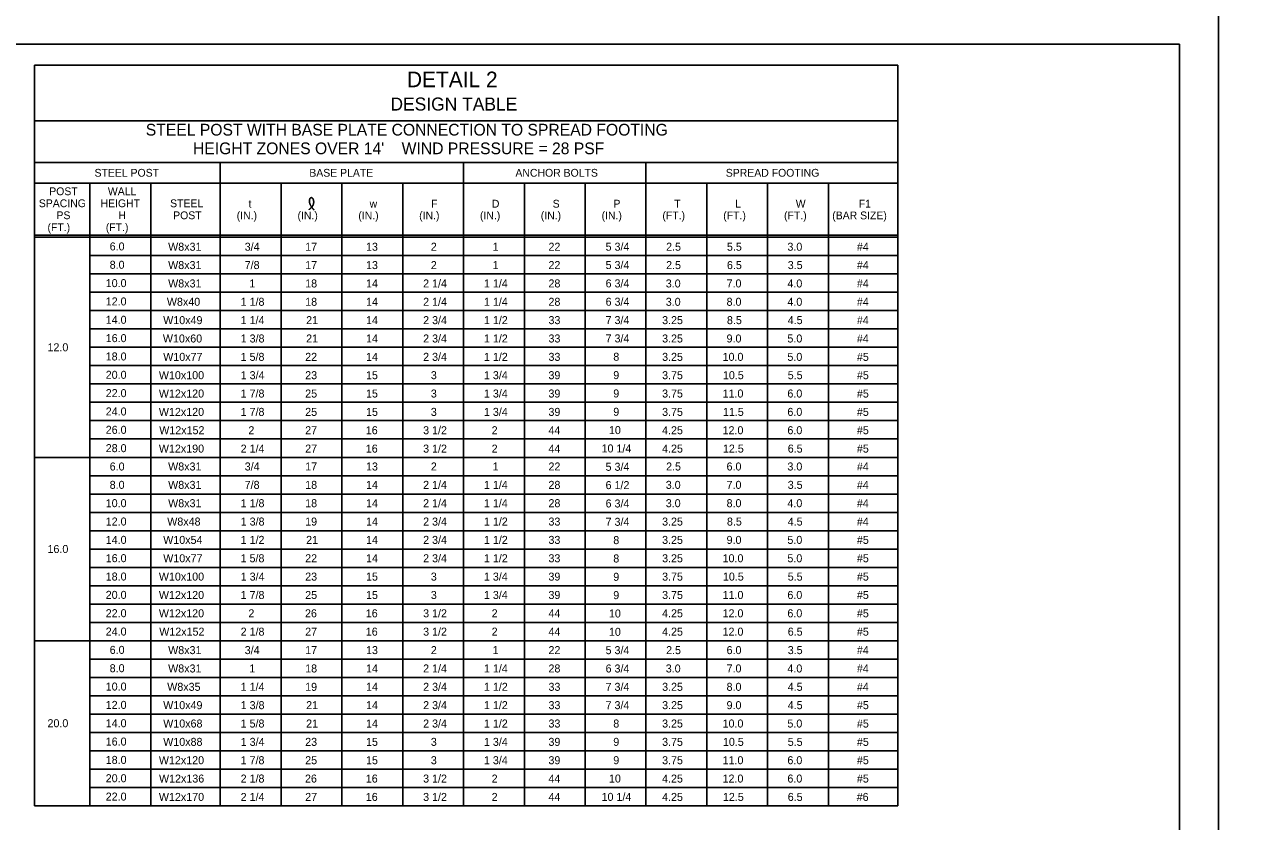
# Model space of a CAD drawing. Extents: x 3475 to 6558, y -3780 to 1166.
# Drawn here: x 4985.3 to 5460.5, y -929.6 to -623.8 of the extents above; entities that cross this region are included whole.
import ezdxf

# ---------------------------------------------------------------- set-up
doc = ezdxf.new("R2010")
doc.units = 0
for name, color, linetype in [('1', 7, 'Continuous'), ('2', 7, 'Continuous'), ('PLT-BNDY', 7, 'Continuous')]:
    doc.layers.add(name, color=color, linetype=linetype)

msp = doc.modelspace()

# ---------------------------------------------------------------- linework, layer by layer
at = {"layer": '1'}
for p, q in [((5320.34, -639.3), (4989.01, -639.3)), ((4989.01, -639.3), (4989.01, -923.63)), ((5320.34, -639.3), (5320.34, -923.63)), ((5320.34, -660.64), (4989.01, -660.64)), ((4989.01, -676.64), (5320.34, -676.64)), ((5060.34, -676.64), (5060.34, -923.63)), ((5153.67, -676.64), (5153.67, -923.63)), ((5223.68, -676.64), (5223.68, -923.63)), ((4989.01, -684.64), (5320.34, -684.64)), ((4989.01, -684.64), (5057.01, -684.64)), ((4989.01, -684.64), (5057.01, -684.64)), ((5010.34, -923.63), (5010.34, -684.64)), ((5033.67, -684.64), (5033.67, -923.63)), ((5083.67, -684.64), (5083.67, -923.63)), ((5107.01, -684.64), (5107.01, -923.63)), ((5130.34, -684.64), (5130.34, -923.63)), ((5177.01, -684.64), (5177.01, -923.63)), ((5200.34, -684.64), (5200.34, -923.63)), ((5247.01, -684.64), (5247.01, -923.63)), ((5270.34, -684.64), (5270.34, -923.63)), ((5293.68, -684.64), (5293.68, -923.63)), ((4989.01, -704.64), (5320.34, -704.64)), ((4989.01, -705.39), (5320.34, -705.39)), ((5010.34, -712.43), (5320.34, -712.43)), ((5010.34, -719.47), (5320.34, -719.47)), ((5010.34, -726.51), (5320.34, -726.51)), ((5010.34, -733.55), (5320.34, -733.55)), ((5010.34, -740.59), (5320.34, -740.59)), ((5010.34, -747.63), (5320.34, -747.63)), ((5010.34, -754.67), (5320.34, -754.67)), ((5010.34, -761.71), (5320.34, -761.71)), ((5010.34, -768.75), (5320.34, -768.75)), ((5010.34, -775.79), (5320.34, -775.79)), ((5010.34, -782.83), (5320.34, -782.83)), ((4989.01, -789.87), (5320.34, -789.87)), ((5010.34, -796.91), (5320.34, -796.91)), ((5010.34, -803.95), (5320.34, -803.95)), ((5010.34, -810.99), (5320.34, -810.99)), ((5010.34, -818.03), (5320.34, -818.03)), ((5010.34, -825.07), (5320.34, -825.07)), ((5010.34, -832.11), (5320.34, -832.11)), ((5010.34, -839.15), (5320.34, -839.15)), ((5010.34, -846.19), (5320.34, -846.19)), ((5010.34, -853.23), (5320.34, -853.23)), ((4989.01, -860.27), (5320.34, -860.27)), ((5010.34, -867.31), (5320.34, -867.31)), ((5010.34, -874.35), (5320.34, -874.35)), ((5010.34, -881.39), (5320.34, -881.39)), ((5010.34, -888.43), (5320.34, -888.43)), ((5010.34, -895.47), (5320.34, -895.47)), ((5010.34, -902.51), (5320.34, -902.51)), ((5010.34, -909.55), (5320.34, -909.55)), ((5010.34, -916.59), (5320.34, -916.59)), ((4989.01, -923.63), (5320.34, -923.63))]:
    msp.add_line(p, q, dxfattribs=at)
msp.add_spline([(5094.4, -694.81), (5094.6, -694.64), (5094.73, -694.51), (5094.93, -694.31), (5095.09, -694.14), (5095.37, -693.94), (5095.56, -693.68), (5095.74, -693.49), (5095.86, -693.26), (5095.97, -693), (5096.05, -692.77), (5096.13, -692.54), (5096.15, -692.35), (5096.19, -692.1), (5096.2, -691.88), (5096.19, -691.63), (5096.14, -691.38), (5096.09, -691.14), (5096.03, -690.91), (5095.95, -690.68), (5095.87, -690.54), (5095.78, -690.44), (5095.68, -690.35), (5095.59, -690.26), (5095.47, -690.2), (5095.39, -690.18), (5095.22, -690.18), (5095.13, -690.2), (5094.98, -690.26), (5094.88, -690.34), (5094.82, -690.42), (5094.76, -690.54), (5094.69, -690.66), (5094.65, -690.8), (5094.61, -690.91), (5094.58, -691.15), (5094.55, -691.32), (5094.58, -691.51), (5094.58, -691.71), (5094.61, -691.98), (5094.64, -692.22), (5094.67, -692.38), (5094.75, -692.6), (5094.85, -692.83), (5094.94, -693.03), (5095.04, -693.22), (5095.16, -693.45), (5095.35, -693.63), (5095.47, -693.84), (5095.61, -694), (5095.72, -694.18), (5095.86, -694.35), (5095.99, -694.52), (5096.1, -694.63), (5096.21, -694.76), (5096.32, -694.93)], degree=3, dxfattribs=at)
at = {"layer": '2'}
for p, q in [((4642.34, -631.31), (5428.34, -631.31)), ((5428.34, -631.31), (5428.34, -1195.31))]:
    msp.add_line(p, q, dxfattribs=at)
at = {"layer": 'PLT-BNDY'}
for points in [[(4602.34, -616.31), (5443.34, -616.31), (5443.34, -1210.31), (4602.34, -1210.31)], [(5443.34, -616.31), (6284.34, -616.31), (6284.34, -1210.31), (5443.34, -1210.31)]]:
    msp.add_lwpolyline(points, close=True, dxfattribs=at)

# ---------------------------------------------------------------- texts
at = {"layer": '1'}
for s, height, p in [('DETAIL 2', 6, (5131.97, -647.79)), ('DESIGN TABLE', 5.0001, (5125.64, -656.74)), ('STEEL POST WITH BASE PLATE CONNECTION TO SPREAD FOOTING', 4.5001, (5031.77, -666.34)), ("HEIGHT ZONES OVER 14'    WIND PRESSURE = 28 PSF", 4.5001, (5049.88, -673.5)), ('STEEL POST', 3, (5012.11, -682.14)), ('BASE PLATE', 3, (5094.51, -682.14)), ('ANCHOR BOLTS', 3, (5173.58, -682.14)), ('SPREAD FOOTING', 3, (5254.3, -682.14)), ('POST', 3, (4994.73, -689.24)), ('WALL', 3, (5017.22, -689.24)), ('SPACING', 3, (4990.73, -693.84)), ('HEIGHT', 3, (5014.4, -693.84)), ('STEEL', 3, (5041.11, -693.86)), ('t', 3, (5071.17, -694)), ('w', 3, (5117.65, -694)), ('F', 3, (5141.26, -694)), ('D', 3, (5164.54, -694)), ('S', 3, (5187.88, -694)), ('P', 3, (5211.2, -694)), ('T', 3, (5234.49, -694)), ('L', 3, (5257.94, -694)), ('W', 3, (5281.14, -694)), ('F1', 3, (5305.31, -694)), ('PS', 3, (4997.49, -698.44)), ('H', 3, (5021.27, -698.44)), ('POST', 3, (5042.28, -698.46)), ('(IN.)', 3, (5066.65, -698.5)), ('(IN.)', 3, (5089.98, -698.5)), ('(IN.)', 3, (5113.31, -698.5)), ('(IN.)', 3, (5136.65, -698.5)), ('(IN.)', 3, (5159.98, -698.5)), ('(IN.)', 3, (5183.31, -698.5)), ('(IN.)', 3, (5206.65, -698.5)), ('(FT.)', 3, (5229.98, -698.5)), ('(FT.)', 3, (5253.32, -698.5)), ('(FT.)', 3, (5276.65, -698.5)), ('(BAR SIZE)', 3, (5295.14, -698.5)), ('(FT.)', 3, (4994.06, -703.04)), ('(FT.)', 3, (5016.43, -703.04)), ('6.0', 3.07, (5017.92, -710.44)), ('W8x31', 3.07, (5040.35, -710.56)), ('3/4', 3.07, (5069.72, -710.56)), ('17', 3.07, (5092.93, -710.56)), ('13', 3.07, (5116.27, -710.56)), ('2', 3.07, (5141.14, -710.56)), ('1', 3.07, (5164.82, -710.56)), ('22', 3.07, (5186.27, -710.56)), ('5 3/4', 3.07, (5208.19, -710.55)), ('2.5', 3.07, (5231.4, -710.56)), ('5.5', 3.07, (5254.74, -710.56)), ('3.0', 3.07, (5277.94, -710.56)), ('#4', 3.07, (5304.6, -710.56)), ('8.0', 3.07, (5017.92, -717.48)), ('W8x31', 3.07, (5040.35, -717.6)), ('7/8', 3.07, (5069.71, -717.6)), ('17', 3.07, (5092.93, -717.6)), ('13', 3.07, (5116.27, -717.6)), ('2', 3.07, (5141.14, -717.6)), ('1', 3.07, (5164.82, -717.6)), ('22', 3.07, (5186.27, -717.6)), ('5 3/4', 3.07, (5208.19, -717.59)), ('2.5', 3.07, (5231.4, -717.6)), ('6.5', 3.07, (5254.74, -717.6)), ('3.5', 3.07, (5278.07, -717.6)), ('#4', 3.07, (5304.6, -717.6)), ('10.0', 3.07, (5016.4, -724.52)), ('W8x31', 3.07, (5040.35, -724.65)), ('1', 3.07, (5071.49, -724.65)), ('18', 3.07, (5092.93, -724.65)), ('14', 3.07, (5116.27, -724.65)), ('2 1/4', 3.07, (5138.18, -724.65)), ('1 1/4', 3.07, (5161.51, -724.65)), ('28', 3.07, (5186.27, -724.65)), ('6 3/4', 3.07, (5208.19, -724.63)), ('3.0', 3.07, (5231.27, -724.65)), ('7.0', 3.07, (5254.6, -724.65)), ('4.0', 3.07, (5277.94, -724.65)), ('#4', 3.07, (5304.6, -724.65)), ('12.0', 3.07, (5016.4, -731.56)), ('W8x40', 3.07, (5039.86, -731.69)), ('1 1/8', 3.07, (5068.17, -731.69)), ('18', 3.07, (5092.93, -731.69)), ('14', 3.07, (5116.27, -731.69)), ('2 1/4', 3.07, (5138.18, -731.69)), ('1 1/4', 3.07, (5161.51, -731.69)), ('28', 3.07, (5186.27, -731.69)), ('6 3/4', 3.07, (5208.19, -731.67)), ('3.0', 3.07, (5231.27, -731.69)), ('8.0', 3.07, (5254.6, -731.69)), ('4.0', 3.07, (5277.94, -731.69)), ('#4', 3.07, (5304.6, -731.69)), ('14.0', 3.07, (5016.4, -738.6)), ('W10x49', 3.07, (5038.45, -738.74)), ('1 1/4', 3.07, (5068.17, -738.74)), ('21', 3.07, (5093.29, -738.74)), ('14', 3.07, (5116.27, -738.74)), ('2 3/4', 3.07, (5138.19, -738.74)), ('1 1/2', 3.07, (5161.51, -738.74)), ('33', 3.07, (5186.27, -738.74)), ('7 3/4', 3.07, (5208.19, -738.71)), ('3.25', 3.07, (5229.87, -738.74)), ('8.5', 3.07, (5254.74, -738.74)), ('4.5', 3.07, (5278.07, -738.74)), ('#4', 3.07, (5304.6, -738.74)), ('16.0', 3.07, (5016.4, -745.64)), ('W10x60', 3.07, (5038.33, -745.78)), ('1 3/8', 3.07, (5068.19, -745.78)), ('21', 3.07, (5093.29, -745.78)), ('14', 3.07, (5116.27, -745.78)), ('2 3/4', 3.07, (5138.19, -745.78)), ('1 1/2', 3.07, (5161.51, -745.78)), ('33', 3.07, (5186.27, -745.78)), ('7 3/4', 3.07, (5208.19, -745.75)), ('3.25', 3.07, (5229.87, -745.78)), ('9.0', 3.07, (5254.6, -745.78)), ('5.0', 3.07, (5277.94, -745.78)), ('#4', 3.07, (5304.6, -745.78)), ('12.0', 3.07, (4994.06, -749.16)), ('18.0', 3.07, (5016.4, -752.68)), ('W10x77', 3.07, (5038.46, -752.83)), ('1 5/8', 3.07, (5068.16, -752.83)), ('22', 3.07, (5092.93, -752.83)), ('14', 3.07, (5116.27, -752.83)), ('2 3/4', 3.07, (5138.19, -752.83)), ('1 1/2', 3.07, (5161.51, -752.83)), ('33', 3.07, (5186.27, -752.83)), ('8', 3.07, (5211.14, -752.79)), ('3.25', 3.07, (5229.87, -752.83)), ('10.0', 3.07, (5253.07, -752.83)), ('5.0', 3.07, (5277.94, -752.83)), ('#5', 3.07, (5304.6, -752.83)), ('20.0', 3.07, (5016.4, -759.72)), ('W10x100', 3.07, (5036.79, -759.87)), ('1 3/4', 3.07, (5068.19, -759.87)), ('23', 3.07, (5092.93, -759.87)), ('15', 3.07, (5116.27, -759.87)), ('3', 3.07, (5141.14, -759.87)), ('1 3/4', 3.07, (5161.52, -759.87)), ('39', 3.07, (5186.26, -759.87)), ('9', 3.07, (5211.13, -759.83)), ('3.75', 3.07, (5229.87, -759.87)), ('10.5', 3.07, (5253.2, -759.87)), ('5.5', 3.07, (5278.07, -759.87)), ('#5', 3.07, (5304.6, -759.87)), ('22.0', 3.07, (5016.4, -766.76)), ('W12x120', 3.07, (5036.79, -766.91)), ('1 7/8', 3.07, (5068.17, -766.91)), ('25', 3.07, (5092.93, -766.91)), ('15', 3.07, (5116.27, -766.91)), ('3', 3.07, (5141.14, -766.91)), ('1 3/4', 3.07, (5161.52, -766.91)), ('39', 3.07, (5186.26, -766.91)), ('9', 3.07, (5211.13, -766.87)), ('3.75', 3.07, (5229.87, -766.91)), ('11.0', 3.07, (5253.07, -766.91)), ('6.0', 3.07, (5277.94, -766.91)), ('#5', 3.07, (5304.6, -766.91)), ('24.0', 3.07, (5016.4, -773.8)), ('W12x120', 3.07, (5036.79, -773.96)), ('1 7/8', 3.07, (5068.17, -773.96)), ('25', 3.07, (5092.93, -773.96)), ('15', 3.07, (5116.27, -773.96)), ('3', 3.07, (5141.14, -773.96)), ('1 3/4', 3.07, (5161.52, -773.96)), ('39', 3.07, (5186.26, -773.96)), ('9', 3.07, (5211.13, -773.91)), ('3.75', 3.07, (5229.87, -773.96)), ('11.5', 3.07, (5253.2, -773.96)), ('6.0', 3.07, (5277.94, -773.96)), ('#5', 3.07, (5304.6, -773.96)), ('26.0', 3.07, (5016.4, -780.84)), ('W12x152', 3.07, (5036.93, -781)), ('2', 3.07, (5071.14, -781)), ('27', 3.07, (5092.93, -781)), ('16', 3.07, (5116.18, -781)), ('3 1/2', 3.07, (5138.18, -781)), ('2', 3.07, (5164.47, -781)), ('44', 3.07, (5186.27, -781)), ('10', 3.07, (5209.47, -780.95)), ('4.25', 3.07, (5229.87, -781)), ('12.0', 3.07, (5253.07, -781)), ('6.0', 3.07, (5277.94, -781)), ('#5', 3.07, (5304.6, -781)), ('28.0', 3.07, (5016.4, -787.88)), ('W12x190', 3.07, (5036.79, -788.05)), ('2 1/4', 3.07, (5068.17, -788.05)), ('27', 3.07, (5092.93, -788.05)), ('16', 3.07, (5116.18, -788.05)), ('3 1/2', 3.07, (5138.18, -788.05)), ('2', 3.07, (5164.47, -788.05)), ('44', 3.07, (5186.27, -788.05)), ('10 1/4', 3.07, (5206.64, -787.99)), ('4.25', 3.07, (5229.87, -788.05)), ('12.5', 3.07, (5253.2, -788.05)), ('6.5', 3.07, (5278.07, -788.05)), ('#5', 3.07, (5304.6, -788.05)), ('6.0', 3.07, (5017.92, -794.92)), ('W8x31', 3.07, (5040.35, -794.92)), ('3/4', 3.07, (5069.72, -794.92)), ('17', 3.07, (5092.93, -794.92)), ('13', 3.07, (5116.27, -794.92)), ('2', 3.07, (5141.14, -794.92)), ('1', 3.07, (5164.82, -794.92)), ('22', 3.07, (5186.27, -794.92)), ('5 3/4', 3.07, (5208.19, -795.03)), ('2.5', 3.07, (5231.4, -794.92)), ('6.0', 3.07, (5254.6, -794.92)), ('3.0', 3.07, (5277.94, -794.92)), ('#4', 3.07, (5304.6, -794.92)), ('8.0', 3.07, (5017.92, -801.96)), ('W8x31', 3.07, (5040.35, -801.97)), ('7/8', 3.07, (5069.71, -801.97)), ('18', 3.07, (5092.93, -801.97)), ('14', 3.07, (5116.27, -801.97)), ('2 1/4', 3.07, (5138.18, -801.97)), ('1 1/4', 3.07, (5161.51, -801.97)), ('28', 3.07, (5186.27, -801.97)), ('6 1/2', 3.07, (5208.18, -802.07)), ('3.0', 3.07, (5231.27, -801.97)), ('7.0', 3.07, (5254.6, -801.97)), ('3.5', 3.07, (5278.07, -801.97)), ('#4', 3.07, (5304.6, -801.97)), ('10.0', 3.07, (5016.4, -809)), ('W8x31', 3.07, (5040.35, -809.01)), ('1 1/8', 3.07, (5068.17, -809.01)), ('18', 3.07, (5092.93, -809.01)), ('14', 3.07, (5116.27, -809.01)), ('2 1/4', 3.07, (5138.18, -809.01)), ('1 1/4', 3.07, (5161.51, -809.01)), ('28', 3.07, (5186.27, -809.01)), ('6 3/4', 3.07, (5208.19, -809.11)), ('3.0', 3.07, (5231.27, -809.01)), ('8.0', 3.07, (5254.6, -809.01)), ('4.0', 3.07, (5277.94, -809.01)), ('#4', 3.07, (5304.6, -809.01)), ('12.0', 3.07, (5016.4, -816.04)), ('W8x48', 3.07, (5040, -816.06)), ('1 3/8', 3.07, (5068.19, -816.06)), ('19', 3.07, (5092.92, -816.06)), ('14', 3.07, (5116.27, -816.06)), ('2 3/4', 3.07, (5138.19, -816.06)), ('1 1/2', 3.07, (5161.51, -816.06)), ('33', 3.07, (5186.27, -816.06)), ('7 3/4', 3.07, (5208.19, -816.15)), ('3.25', 3.07, (5229.87, -816.06)), ('8.5', 3.07, (5254.74, -816.06)), ('4.5', 3.07, (5278.07, -816.06)), ('#4', 3.07, (5304.6, -816.06)), ('14.0', 3.07, (5016.4, -823.08)), ('W10x54', 3.07, (5038.46, -823.1)), ('1 1/2', 3.07, (5068.17, -823.1)), ('21', 3.07, (5093.29, -823.1)), ('14', 3.07, (5116.27, -823.1)), ('2 3/4', 3.07, (5138.19, -823.1)), ('1 1/2', 3.07, (5161.51, -823.1)), ('33', 3.07, (5186.27, -823.1)), ('8', 3.07, (5211.14, -823.19)), ('3.25', 3.07, (5229.87, -823.1)), ('9.0', 3.07, (5254.6, -823.1)), ('5.0', 3.07, (5277.94, -823.1)), ('#5', 3.07, (5304.6, -823.1)), ('16.0', 3.07, (4994.06, -826.6)), ('16.0', 3.07, (5016.4, -830.12)), ('W10x77', 3.07, (5038.46, -830.15)), ('1 5/8', 3.07, (5068.16, -830.15)), ('22', 3.07, (5092.93, -830.15)), ('14', 3.07, (5116.27, -830.15)), ('2 3/4', 3.07, (5138.19, -830.15)), ('1 1/2', 3.07, (5161.51, -830.15)), ('33', 3.07, (5186.27, -830.15)), ('8', 3.07, (5211.14, -830.23)), ('3.25', 3.07, (5229.87, -830.15)), ('10.0', 3.07, (5253.07, -830.15)), ('5.0', 3.07, (5277.94, -830.15)), ('#5', 3.07, (5304.6, -830.15)), ('18.0', 3.07, (5016.4, -837.16)), ('W10x100', 3.07, (5036.79, -837.19)), ('1 3/4', 3.07, (5068.19, -837.19)), ('23', 3.07, (5092.93, -837.19)), ('15', 3.07, (5116.27, -837.19)), ('3', 3.07, (5141.14, -837.19)), ('1 3/4', 3.07, (5161.52, -837.19)), ('39', 3.07, (5186.26, -837.19)), ('9', 3.07, (5211.13, -837.27)), ('3.75', 3.07, (5229.87, -837.19)), ('10.5', 3.07, (5253.2, -837.19)), ('5.5', 3.07, (5278.07, -837.19)), ('#5', 3.07, (5304.6, -837.19)), ('1 7/8', 3.07, (5068.17, -844.24)), ('1 3/4', 3.07, (5161.52, -844.24)), ('20.0', 3.07, (5016.4, -844.2)), ('W12x120', 3.07, (5036.79, -844.24)), ('25', 3.07, (5092.93, -844.24)), ('15', 3.07, (5116.27, -844.24)), ('3', 3.07, (5141.14, -844.24)), ('39', 3.07, (5186.26, -844.24)), ('9', 3.07, (5211.13, -844.31)), ('3.75', 3.07, (5229.87, -844.24)), ('11.0', 3.07, (5253.07, -844.24)), ('6.0', 3.07, (5277.94, -844.24)), ('#5', 3.07, (5304.6, -844.24)), ('22.0', 3.07, (5016.4, -851.24)), ('W12x120', 3.07, (5036.79, -851.28)), ('2', 3.07, (5071.14, -851.28)), ('26', 3.07, (5092.85, -851.28)), ('16', 3.07, (5116.18, -851.28)), ('3 1/2', 3.07, (5138.18, -851.28)), ('2', 3.07, (5164.47, -851.28)), ('44', 3.07, (5186.27, -851.28)), ('10', 3.07, (5209.47, -851.35)), ('4.25', 3.07, (5229.87, -851.28)), ('12.0', 3.07, (5253.07, -851.28)), ('6.0', 3.07, (5277.94, -851.28)), ('#5', 3.07, (5304.6, -851.28)), ('24.0', 3.07, (5016.4, -858.28)), ('W12x152', 3.07, (5036.93, -858.32)), ('2 1/8', 3.07, (5068.17, -858.32)), ('27', 3.07, (5092.93, -858.32)), ('16', 3.07, (5116.18, -858.32)), ('3 1/2', 3.07, (5138.18, -858.32)), ('2', 3.07, (5164.47, -858.32)), ('44', 3.07, (5186.27, -858.32)), ('10', 3.07, (5209.47, -858.39)), ('4.25', 3.07, (5229.87, -858.32)), ('12.0', 3.07, (5253.07, -858.32)), ('6.5', 3.07, (5278.07, -858.32)), ('#5', 3.07, (5304.6, -858.32)), ('6.0', 3.07, (5017.92, -865.32)), ('W8x31', 3.07, (5040.35, -865.41)), ('3/4', 3.07, (5069.72, -865.41)), ('17', 3.07, (5092.93, -865.41)), ('13', 3.07, (5116.27, -865.41)), ('2', 3.07, (5141.14, -865.41)), ('1', 3.07, (5164.82, -865.41)), ('22', 3.07, (5186.27, -865.41)), ('5 3/4', 3.07, (5208.19, -865.43)), ('2.5', 3.07, (5231.4, -865.41)), ('6.0', 3.07, (5254.6, -865.41)), ('3.5', 3.07, (5278.07, -865.41)), ('#4', 3.07, (5304.6, -865.41)), ('8.0', 3.07, (5017.92, -872.36)), ('W8x31', 3.07, (5040.35, -872.45)), ('1', 3.07, (5071.49, -872.45)), ('18', 3.07, (5092.93, -872.45)), ('14', 3.07, (5116.27, -872.45)), ('2 1/4', 3.07, (5138.18, -872.45)), ('1 1/4', 3.07, (5161.51, -872.45)), ('28', 3.07, (5186.27, -872.45)), ('6 3/4', 3.07, (5208.19, -872.47)), ('3.0', 3.07, (5231.27, -872.45)), ('7.0', 3.07, (5254.6, -872.45)), ('4.0', 3.07, (5277.94, -872.45)), ('#4', 3.07, (5304.6, -872.45)), ('10.0', 3.07, (5016.4, -879.4)), ('W8x35', 3.07, (5040, -879.5)), ('1 1/4', 3.07, (5068.17, -879.5)), ('19', 3.07, (5092.92, -879.5)), ('14', 3.07, (5116.27, -879.5)), ('2 3/4', 3.07, (5138.19, -879.5)), ('1 1/2', 3.07, (5161.51, -879.5)), ('33', 3.07, (5186.27, -879.5)), ('7 3/4', 3.07, (5208.19, -879.51)), ('3.25', 3.07, (5229.87, -879.5)), ('8.0', 3.07, (5254.6, -879.5)), ('4.5', 3.07, (5278.07, -879.5)), ('#4', 3.07, (5304.6, -879.5)), ('12.0', 3.07, (5016.4, -886.44)), ('W10x49', 3.07, (5038.45, -886.54)), ('1 3/8', 3.07, (5068.19, -886.54)), ('21', 3.07, (5093.29, -886.54)), ('14', 3.07, (5116.27, -886.54)), ('2 3/4', 3.07, (5138.19, -886.54)), ('1 1/2', 3.07, (5161.51, -886.54)), ('33', 3.07, (5186.27, -886.54)), ('7 3/4', 3.07, (5208.19, -886.55)), ('3.25', 3.07, (5229.87, -886.54)), ('9.0', 3.07, (5254.6, -886.54)), ('4.5', 3.07, (5278.07, -886.54)), ('#5', 3.07, (5304.6, -886.54)), ('20.0', 3.07, (4994.06, -893.48)), ('14.0', 3.07, (5016.4, -893.48)), ('W10x68', 3.07, (5038.46, -893.59)), ('1 5/8', 3.07, (5068.16, -893.59)), ('21', 3.07, (5093.29, -893.59)), ('14', 3.07, (5116.27, -893.59)), ('2 3/4', 3.07, (5138.19, -893.59)), ('1 1/2', 3.07, (5161.51, -893.59)), ('33', 3.07, (5186.27, -893.59)), ('8', 3.07, (5211.14, -893.59)), ('3.25', 3.07, (5229.87, -893.59)), ('10.0', 3.07, (5253.07, -893.59)), ('5.0', 3.07, (5277.94, -893.59)), ('#5', 3.07, (5304.6, -893.59)), ('16.0', 3.07, (5016.4, -900.52)), ('W10x88', 3.07, (5038.46, -900.63)), ('1 3/4', 3.07, (5068.19, -900.63)), ('23', 3.07, (5092.93, -900.63)), ('15', 3.07, (5116.27, -900.63)), ('3', 3.07, (5141.14, -900.63)), ('1 3/4', 3.07, (5161.52, -900.63)), ('39', 3.07, (5186.26, -900.63)), ('9', 3.07, (5211.13, -900.63)), ('3.75', 3.07, (5229.87, -900.63)), ('10.5', 3.07, (5253.2, -900.63)), ('5.5', 3.07, (5278.07, -900.63)), ('#5', 3.07, (5304.6, -900.63)), ('18.0', 3.07, (5016.4, -907.56)), ('W12x120', 3.07, (5036.79, -907.68)), ('1 7/8', 3.07, (5068.17, -907.68)), ('25', 3.07, (5092.93, -907.68)), ('15', 3.07, (5116.27, -907.68)), ('3', 3.07, (5141.14, -907.68)), ('1 3/4', 3.07, (5161.52, -907.68)), ('39', 3.07, (5186.26, -907.68)), ('9', 3.07, (5211.13, -907.67)), ('3.75', 3.07, (5229.87, -907.68)), ('11.0', 3.07, (5253.07, -907.68)), ('6.0', 3.07, (5277.94, -907.68)), ('#5', 3.07, (5304.6, -907.68)), ('20.0', 3.07, (5016.4, -914.6)), ('W12x136', 3.07, (5036.84, -914.72)), ('2 1/8', 3.07, (5068.17, -914.72)), ('26', 3.07, (5092.85, -914.72)), ('16', 3.07, (5116.18, -914.72)), ('3 1/2', 3.07, (5138.18, -914.72)), ('2', 3.07, (5164.47, -914.72)), ('44', 3.07, (5186.27, -914.72)), ('10', 3.07, (5209.47, -914.71)), ('4.25', 3.07, (5229.87, -914.72)), ('12.0', 3.07, (5253.07, -914.72)), ('6.0', 3.07, (5277.94, -914.72)), ('#5', 3.07, (5304.6, -914.72)), ('22.0', 3.07, (5016.4, -921.64)), ('W12x170', 3.07, (5036.79, -921.77)), ('2 1/4', 3.07, (5068.17, -921.77)), ('27', 3.07, (5092.93, -921.77)), ('16', 3.07, (5116.18, -921.77)), ('3 1/2', 3.07, (5138.18, -921.77)), ('2', 3.07, (5164.47, -921.77)), ('44', 3.07, (5186.27, -921.77)), ('10 1/4', 3.07, (5206.64, -921.75)), ('4.25', 3.07, (5229.87, -921.77)), ('12.5', 3.07, (5253.2, -921.77)), ('6.5', 3.07, (5278.07, -921.77)), ('#6', 3.07, (5304.52, -921.77))]:
    msp.add_text(s, height=height, dxfattribs=at).set_placement(p)

doc.saveas('drawing.dxf')
